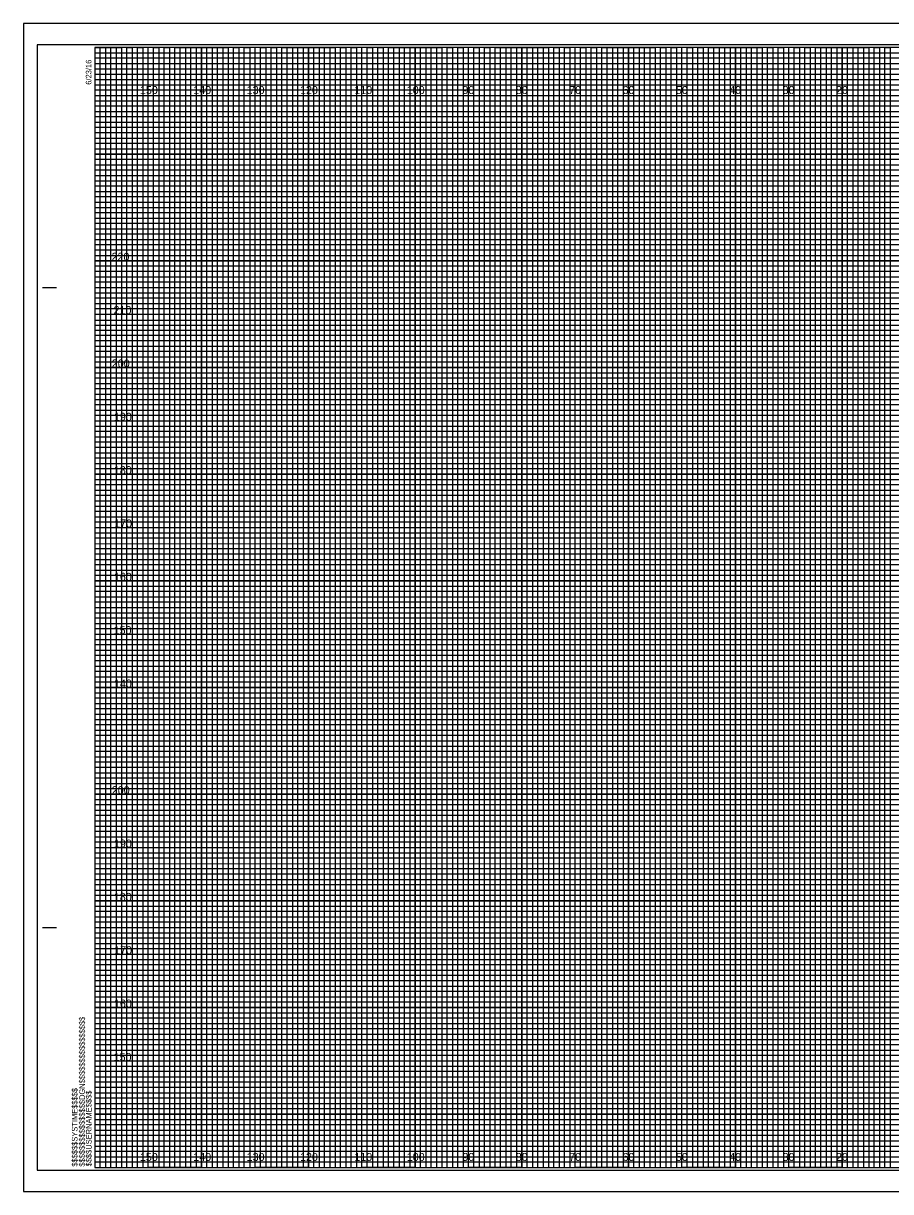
# Model space of a CAD drawing. Extents: x -13 to 323, y -5 to 1754.
# Drawn here: x -13.4 to 149.1, y 435.5 to 654.5 of the extents above; entities that cross this region are included whole.
import ezdxf

# ---------------------------------------------------------------- set-up
doc = ezdxf.new("R2010")
doc.units = 0
for name, color, linetype in [('Exist Cross Section Cell', 7, 'Continuous'), ('Exist XS Center Line Elevation Label', 7, 'Continuous'), ('Exist XS Ground Line', 7, 'Continuous'), ('Prop CMT Pvmt Course 1', 7, 'Continuous'), ('Prop CMT Pvmt Course 2', 7, 'Continuous'), ('Prop CMT Pvmt Course 3', 7, 'Continuous'), ('Prop CMT Shld Paved Course 1', 7, 'Continuous'), ('Prop CMT Shld Paved Course 2', 7, 'Continuous'), ('Prop CMT Subgrade Earthwork', 7, 'Continuous'), ('Prop XS Ditch Standard Text', 7, 'Continuous'), ('Scratch_Level_0', 7, 'Continuous')]:
    doc.layers.add(name, color=color, linetype=linetype)

msp = doc.modelspace()

# ---------------------------------------------------------------- linework, layer by layer
at = {"layer": 'Exist XS Center Line Elevation Label'}
for points in [[(0, 650), (5, 650), (5, 440), (15, 440), (15, 650), (25, 650), (25, 440), (35, 440), (35, 650), (45, 650), (45, 440), (55, 440), (55, 650), (65, 650), (65, 440), (75, 440), (75, 650), (85, 650), (85, 440), (95, 440), (95, 650), (105, 650), (105, 440), (115, 440), (115, 650), (125, 650), (125, 440), (135, 440), (135, 650), (145, 650), (145, 440), (155, 440)], [(0, 645), (275, 645)], [(0, 625), (320, 625), (320, 635), (0, 635)], [(0, 605), (320, 605), (320, 615), (0, 615)], [(0, 585), (320, 585), (320, 595), (0, 595)], [(0, 565), (320, 565), (320, 575), (0, 575)], [(0, 545), (320, 545), (320, 555), (0, 555)], [(0, 525), (320, 525), (320, 535), (0, 535)], [(0, 505), (320, 505), (320, 515), (0, 515)], [(0, 485), (320, 485), (320, 495), (0, 495)], [(0, 465), (320, 465), (320, 475), (0, 475)], [(0, 445), (320, 445), (320, 455), (0, 455)]]:
    msp.add_lwpolyline(points, dxfattribs=at)
at = {"layer": 'Exist XS Ground Line'}
for p, q in [((10, 650), (0, 650)), ((10, 440), (10, 650)), ((30, 650), (20, 650)), ((20, 650), (20, 440)), ((30, 440), (30, 650)), ((50, 650), (40, 650)), ((40, 650), (40, 440)), ((50, 440), (50, 650)), ((70, 650), (60, 650)), ((60, 650), (60, 440)), ((70, 440), (70, 650)), ((90, 650), (80, 650)), ((80, 650), (80, 440)), ((90, 440), (90, 650)), ((110, 650), (100, 650)), ((100, 650), (100, 440)), ((110, 440), (110, 650)), ((130, 650), (120, 650)), ((120, 650), (120, 440)), ((130, 440), (130, 650)), ((150, 650), (140, 650)), ((140, 650), (140, 440)), ((20, 440), (10, 440)), ((40, 440), (30, 440)), ((60, 440), (50, 440)), ((80, 440), (70, 440)), ((100, 440), (90, 440)), ((120, 440), (110, 440)), ((140, 440), (130, 440))]:
    msp.add_line(p, q, dxfattribs=at)
for points in [[(0, 640), (320, 640), (320, 630), (0, 630)], [(0, 620), (320, 620), (320, 610), (0, 610)], [(0, 600), (320, 600), (320, 590), (0, 590)], [(0, 580), (320, 580), (320, 570), (0, 570)], [(0, 560), (320, 560), (320, 550), (0, 550)], [(0, 540), (320, 540), (320, 530), (0, 530)], [(0, 520), (320, 520), (320, 510), (0, 510)], [(0, 500), (320, 500), (320, 490), (0, 490)], [(0, 480), (320, 480), (320, 470), (0, 470)], [(0, 460), (320, 460), (320, 450), (0, 450)]]:
    msp.add_lwpolyline(points, dxfattribs=at)
at = {"layer": 'Prop CMT Pvmt Course 1'}
for p, q in [((323.3, 654.5), (-13.4, 654.5)), ((-13.4, 654.5), (-13.4, 435.5)), ((-13.4, 435.5), (323.3, 435.5))]:
    msp.add_line(p, q, dxfattribs=at)
at = {"layer": 'Prop CMT Pvmt Course 2'}
msp.add_lwpolyline([(-13.4, 435.5), (323.3, 435.5), (323.3, 654.5), (-13.4, 654.5)], close=True, dxfattribs=at)
at = {"layer": 'Prop CMT Pvmt Course 3'}
msp.add_lwpolyline([(-10.8, 439.5), (322.4, 439.5), (322.4, 650.5), (-10.8, 650.5)], close=True, dxfattribs=at)
at = {"layer": 'Prop CMT Shld Paved Course 1'}
for p, q in [((-9.8, 605), (-7.3, 605)), ((-9.7, 605), (-7.2, 605)), ((-9.8, 485), (-7.3, 485)), ((-9.7, 485), (-7.2, 485)), ((0, 440), (0, 440)), ((0, 440), (0, 440)), ((0, 440), (0, 440)), ((0, 440), (0, 440)), ((0, 440), (0, 440)), ((0, 440), (0, 440)), ((0, 440), (0, 440))]:
    msp.add_line(p, q, dxfattribs=at)
msp.add_lwpolyline([(320, 650), (0, 650), (0, 440), (320, 440)], close=True, dxfattribs=at)
at = {"layer": 'Prop CMT Shld Paved Course 2'}
for points in [[(0, 440), (1, 440), (1, 650), (2, 650), (2, 440)], [(2, 440), (3, 440), (3, 650), (4, 650), (4, 440)], [(5, 440), (6, 440), (6, 650), (7, 650), (7, 440)], [(7, 440), (8, 440), (8, 650), (9, 650), (9, 440)], [(10, 440), (11, 440), (11, 650), (12, 650), (12, 440)], [(12, 440), (13, 440), (13, 650), (14, 650), (14, 440)], [(15, 440), (16, 440), (16, 650), (17, 650), (17, 440)], [(17, 440), (18, 440), (18, 650), (19, 650), (19, 440)], [(20, 440), (21, 440), (21, 650), (22, 650), (22, 440)], [(22, 440), (23, 440), (23, 650), (24, 650), (24, 440)], [(25, 440), (26, 440), (26, 650), (27, 650), (27, 440)], [(27, 440), (28, 440), (28, 650), (29, 650), (29, 440)], [(30, 440), (31, 440), (31, 650), (32, 650), (32, 440)], [(32, 440), (33, 440), (33, 650), (34, 650), (34, 440)], [(35, 440), (36, 440), (36, 650), (37, 650), (37, 440)], [(37, 440), (38, 440), (38, 650), (39, 650), (39, 440)], [(40, 440), (41, 440), (41, 650), (42, 650), (42, 440)], [(42, 440), (43, 440), (43, 650), (44, 650), (44, 440)], [(45, 440), (46, 440), (46, 650), (47, 650), (47, 440)], [(47, 440), (48, 440), (48, 650), (49, 650), (49, 440)], [(50, 440), (51, 440), (51, 650), (52, 650), (52, 440)], [(52, 440), (53, 440), (53, 650), (54, 650), (54, 440)], [(55, 440), (56, 440), (56, 650), (57, 650), (57, 440)], [(57, 440), (58, 440), (58, 650), (59, 650), (59, 440)], [(60, 440), (61, 440), (61, 650), (62, 650), (62, 440)], [(62, 440), (63, 440), (63, 650), (64, 650), (64, 440)], [(65, 440), (66, 440), (66, 650), (67, 650), (67, 440)], [(67, 440), (68, 440), (68, 650), (69, 650), (69, 440)], [(70, 440), (71, 440), (71, 650), (72, 650), (72, 440)], [(72, 440), (73, 440), (73, 650), (74, 650), (74, 440)], [(75, 440), (76, 440), (76, 650), (77, 650), (77, 440)], [(77, 440), (78, 440), (78, 650), (79, 650), (79, 440)], [(80, 440), (81, 440), (81, 650), (82, 650), (82, 440)], [(82, 440), (83, 440), (83, 650), (84, 650), (84, 440)], [(85, 440), (86, 440), (86, 650), (87, 650), (87, 440)], [(87, 440), (88, 440), (88, 650), (89, 650), (89, 440)], [(90, 440), (91, 440), (91, 650), (92, 650), (92, 440)], [(92, 440), (93, 440), (93, 650), (94, 650), (94, 440)], [(95, 440), (96, 440), (96, 650), (97, 650), (97, 440)], [(97, 440), (98, 440), (98, 650), (99, 650), (99, 440)], [(100, 440), (101, 440), (101, 650), (102, 650), (102, 440)], [(102, 440), (103, 440), (103, 650), (104, 650), (104, 440)], [(105, 440), (106, 440), (106, 650), (107, 650), (107, 440)], [(107, 440), (108, 440), (108, 650), (109, 650), (109, 440)], [(110, 440), (111, 440), (111, 650), (112, 650), (112, 440)], [(112, 440), (113, 440), (113, 650), (114, 650), (114, 440)], [(115, 440), (116, 440), (116, 650), (117, 650), (117, 440)], [(117, 440), (118, 440), (118, 650), (119, 650), (119, 440)], [(120, 440), (121, 440), (121, 650), (122, 650), (122, 440)], [(122, 440), (123, 440), (123, 650), (124, 650), (124, 440)], [(125, 440), (126, 440), (126, 650), (127, 650), (127, 440)], [(127, 440), (128, 440), (128, 650), (129, 650), (129, 440)], [(130, 440), (131, 440), (131, 650), (132, 650), (132, 440)], [(132, 440), (133, 440), (133, 650), (134, 650), (134, 440)], [(135, 440), (136, 440), (136, 650), (137, 650), (137, 440)], [(137, 440), (138, 440), (138, 650), (139, 650), (139, 440)], [(140, 440), (141, 440), (141, 650), (142, 650), (142, 440)], [(142, 440), (143, 440), (143, 650), (144, 650), (144, 440)], [(145, 440), (146, 440), (146, 650), (147, 650), (147, 440)], [(147, 440), (148, 440), (148, 650), (149, 650), (149, 440)]]:
    msp.add_lwpolyline(points, dxfattribs=at)
at = {"layer": 'Prop CMT Subgrade Earthwork'}
for p, q in [((10, 440), (10, 650)), ((20, 440), (20, 650)), ((30, 440), (30, 650)), ((40, 440), (40, 650)), ((50, 440), (50, 650)), ((60, 440), (60, 650)), ((70, 440), (70, 650)), ((80, 440), (80, 650)), ((90, 440), (90, 650)), ((100, 440), (100, 650)), ((110, 440), (110, 650)), ((120, 440), (120, 650)), ((130, 440), (130, 650)), ((140, 440), (140, 650)), ((0, 640), (320, 640)), ((0, 630), (320, 630)), ((0, 620), (320, 620)), ((0, 610), (320, 610)), ((0, 600), (320, 600)), ((0, 590), (320, 590)), ((0, 580), (320, 580)), ((0, 570), (320, 570)), ((0, 560), (320, 560)), ((0, 550), (320, 550)), ((0, 540), (320, 540)), ((0, 530), (320, 530)), ((0, 520), (320, 520)), ((0, 510), (320, 510)), ((0, 500), (320, 500)), ((0, 490), (320, 490)), ((0, 480), (320, 480)), ((0, 470), (320, 470)), ((0, 460), (320, 460)), ((0, 450), (320, 450))]:
    msp.add_line(p, q, dxfattribs=at)
at = {"layer": 'Scratch_Level_0'}
for p, q in [((0, 649), (260, 649)), ((260, 647.98), (0, 647.98)), ((0, 647.98), (0, 647)), ((0, 647), (260, 647)), ((260, 645.89), (0, 645.89)), ((0, 645.89), (0, 644)), ((0, 644), (320, 644))]:
    msp.add_line(p, q, dxfattribs=at)
for points in [[(0, 643), (270, 643), (320, 643), (320, 642), (0, 642)], [(0, 641), (320, 641), (320, 639), (0, 639)], [(0, 638), (320, 638), (320, 637), (0, 636.98)], [(0, 636), (320, 636), (320, 634), (0, 634)], [(0, 633), (320, 633), (320, 632), (0, 632)], [(0, 631), (320, 631), (320, 629), (0, 629)], [(0, 628), (320, 628), (320, 627), (0, 627)], [(0, 626), (320, 626), (320, 624), (0, 624)], [(0, 623), (320, 623), (320, 622), (0, 622)], [(0, 621), (320, 621), (320, 619), (0, 619)], [(0, 618), (320, 618), (320, 617), (0, 617)], [(0, 616), (320, 616), (320, 613.95), (320, 613), (320, 612), (0, 612)], [(0, 614), (320, 614), (320, 613), (0, 613)], [(0, 611), (320, 611), (320, 609), (0, 609.03)], [(0, 609.03), (320, 609), (320, 608), (0, 608)], [(0, 607), (320, 607), (320, 606), (0, 606)], [(0, 604), (320, 604), (320, 603), (0, 603)], [(0, 602), (320, 602), (320, 601), (0, 601)], [(-0.07, 598.89), (320, 598.89), (320, 597.88), (-0.07, 597.88)], [(0, 597), (320, 597), (320, 596), (0, 596)], [(0, 594), (320, 594), (320, 593), (0, 593)], [(0, 592), (320, 592), (320, 591), (0, 591)], [(0, 589), (320, 589), (320, 588), (0, 588)], [(0, 587), (320, 587), (320, 586), (0, 586)], [(0, 584), (320, 584), (320, 583), (0, 583)], [(0, 582), (320, 582), (320, 581), (0, 581)], [(0, 579), (320, 579), (319.99, 577.98), (0, 578)], [(0, 577), (320, 577), (320, 576), (0, 576)], [(0, 574), (320, 574), (320, 573), (0, 573)], [(0, 572), (320, 572), (320, 571), (0, 571)], [(0, 569), (320, 569), (320, 568), (0, 568)], [(0, 567), (320, 567), (320, 566), (0, 566)], [(0, 564), (320, 564), (320, 563), (0, 563)], [(0, 562), (320, 562), (320, 561), (0, 561)], [(0, 559), (320, 559), (320, 558), (0, 558)], [(0, 556.99), (320.07, 556.91), (320, 556), (0, 556)], [(0, 554), (320, 554), (320, 553), (0, 553)], [(0, 552), (320, 552), (320, 551), (0, 551)], [(0, 549), (320, 549), (320, 548), (0, 548)], [(0, 547), (320, 547), (320, 546), (0, 546)], [(0, 544), (320, 544), (320, 543), (0, 543)], [(0, 542), (320, 542), (320, 541), (0, 541)], [(0, 539), (320, 539), (320, 538), (0, 538)], [(0, 537), (320, 537), (320, 536), (0, 536)], [(0, 534), (320, 534), (320, 533), (0, 533)], [(0, 532), (320, 532), (320, 531), (0, 531)], [(0, 529), (320, 529), (320, 528), (0, 528)], [(0, 527), (320, 527), (320, 526), (0, 526)], [(0, 524), (320, 524), (320, 523), (0, 523)], [(0, 522), (320, 522), (320, 521), (0, 521)], [(0, 519), (320, 519), (319.99, 517.98), (0, 518)], [(0, 517), (320, 517), (320, 516), (0, 516)], [(0, 514), (320, 514), (320, 513), (0, 513)], [(0, 512), (320, 512), (320, 511), (0, 511)], [(0, 509), (320, 509), (320, 508), (0, 508)], [(0, 507), (320, 507), (320, 506), (0, 506)], [(0, 504), (320, 504), (320, 503), (0, 503)], [(0, 502), (320, 502), (320, 501), (0, 501)], [(0, 499), (320, 499), (320, 498), (0, 498)], [(0, 496.99), (320.07, 496.91), (320, 496), (0, 496)], [(0, 494), (320, 494), (320, 493), (0, 493)], [(0, 492), (320, 492), (320, 491), (0, 491)], [(0, 489), (320, 489), (320, 488), (0, 488)], [(0, 487), (320, 487), (320, 486), (0, 486)], [(0, 484), (320, 484), (320, 483), (0, 483)], [(0, 482), (320, 482), (320, 481), (0, 481)], [(0, 479), (320, 479), (320, 478), (0, 478)], [(0, 477), (320, 477), (320, 476), (0, 476)], [(0, 474), (320, 474), (320, 473), (0, 473)], [(0, 472), (320, 472), (320, 471), (0, 471)], [(0, 469), (320, 469), (320, 468), (0, 468)], [(0, 467), (320, 467), (320, 466), (0, 466)], [(0, 464), (320, 464), (320, 463), (0, 463)], [(0, 462), (320, 462), (320, 461), (0, 461)], [(0, 459), (320, 459), (320, 458), (0, 458)], [(0, 457), (320, 457), (320, 456), (0, 456)], [(0, 454), (320, 454), (320, 453), (0, 453)], [(0, 452), (320, 452), (320, 451), (0, 451)], [(0, 449), (320, 449), (320, 448), (0, 448)], [(0, 447), (320, 447), (320, 446), (0, 446)], [(0, 444), (320, 444), (320, 443), (0, 443)], [(0, 442), (320, 442), (320, 441), (0, 441)]]:
    msp.add_lwpolyline(points, dxfattribs=at)

# ---------------------------------------------------------------- texts
at = {"layer": 'Exist Cross Section Cell'}
for s, p in [('220', (3.12, 610)), ('210', (3.5, 600)), ('200', (3.17, 590)), ('190', (3.57, 580)), ('180', (3.55, 570)), ('170', (3.61, 560)), ('160', (3.57, 550)), ('150', (3.52, 540)), ('140', (3.57, 530)), ('200', (3.17, 510)), ('190', (3.57, 500)), ('180', (3.55, 490)), ('170', (3.61, 480)), ('160', (3.57, 470)), ('150', (3.52, 460))]:
    msp.add_text(s, height=1.5, dxfattribs=at).set_placement(p)
at = {"layer": 'Prop CMT Shld Paved Course 1'}
for s, p in [('6/23/16', (-0.65, 643)), ('$$$$$$$$$$$$$$$$DGN$$$$$$$$$$$$$$$$', (-1.88, 440.18)), ('$$$$$$SYSTIME$$$$$', (-3.26, 440.18)), ('$$$$USERNAME$$$$', (-0.62, 440.23))]:
    msp.add_text(s, height=1.05, rotation=90, dxfattribs=at).set_placement(p)
at = {"layer": 'Prop XS Ditch Standard Text'}
for s, p in [('150', (8.44, 641.25)), ('140', (18.44, 641.25)), ('130', (28.44, 641.25)), ('120', (38.44, 641.25)), ('110', (48.62, 641.25)), ('100', (58.44, 641.25)), ('90', (68.86, 641.25)), ('80', (78.86, 641.25)), ('70', (88.86, 641.25)), ('60', (98.86, 641.25)), ('50', (108.86, 641.25)), ('40', (118.86, 641.25)), ('30', (128.86, 641.25)), ('20', (138.86, 641.25)), ('150', (8.44, 441.25)), ('140', (18.44, 441.25)), ('130', (28.44, 441.25)), ('120', (38.44, 441.25)), ('110', (48.62, 441.25)), ('100', (58.44, 441.25)), ('90', (68.86, 441.25)), ('80', (78.86, 441.25)), ('70', (88.86, 441.25)), ('60', (98.86, 441.25)), ('50', (108.86, 441.25)), ('40', (118.86, 441.25)), ('30', (128.86, 441.25)), ('20', (138.86, 441.25))]:
    msp.add_text(s, height=1.5, dxfattribs=at).set_placement(p)

doc.saveas('drawing.dxf')
